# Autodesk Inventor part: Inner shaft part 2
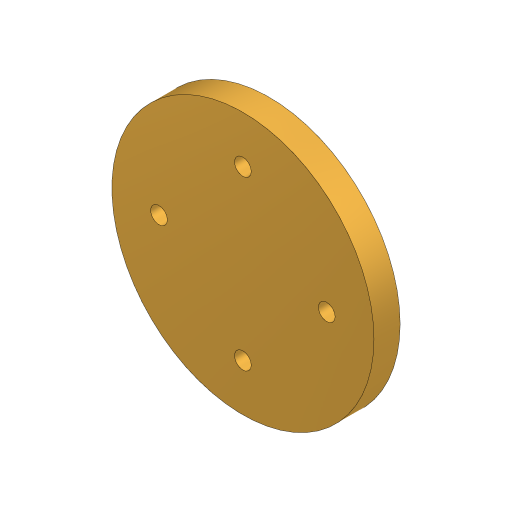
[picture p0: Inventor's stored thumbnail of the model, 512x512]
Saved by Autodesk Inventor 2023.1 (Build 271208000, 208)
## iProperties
Created: 2020-02
Part Number: Inner shaft part 2
Material: Brass, Soft Yellow
Document SubType Name: Modeling
Designer: ftrauzettel
Density: 8.47 g/cm^3
Appearance: Brass - Satin
Sending System: SolidWorks 2016
Last Author: Pam
Last Saved: 2020-07-19
Author: ftrauzettel
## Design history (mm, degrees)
feature "Tap Drill Slot for M2 Tap1"
body "Solid1"
